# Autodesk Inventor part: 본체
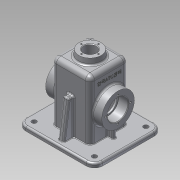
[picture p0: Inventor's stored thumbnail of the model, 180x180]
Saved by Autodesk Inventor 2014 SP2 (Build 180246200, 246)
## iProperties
Created: 2016-08
Part Number: 본체
Material: 알루미늄 6061
Document SubType Name: Modeling
Designer: 402-32
Density: 2.71 g/cm^3
Appearance: 알루미늄 - 평지
Mass: 796.088 g
Surface Area: 911.213 cm^2
Volume: 293.76 cm^3
Author: 402-32
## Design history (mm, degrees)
sketch "스케치1"
  geometry: L1 (-60, -52.5)-(60, -52.5); L2 (60, -52.5)-(60, 52.5); L3 (60, 52.5)-(-60, 52.5); L4 (-60, 52.5)-(-60, -52.5); L5 (-60, -52.5)-(60, 52.5); L6 (60, -52.5)-(-60, 52.5); 1 further point
  constraints: 12 end point, 2 midpoint, 2 parallel, 1 horizontal, 1 perpendicular
  dimensions: "d0" = 120 distance of L3.end L2.end; "d1" = 105 distance of L2.end L1.end
extrude "돌출1" new body sketch "스케치1" distance "d2" = 3; taper "d3" = 0 deg
sketch "스케치2"
  geometry: L1 (-65, -57.5)-(65, -57.5); L2 (65, -57.5)-(65, 57.5); L3 (65, 57.5)-(-65, 57.5); L4 (-65, 57.5)-(-65, -57.5); L5 (-65, -57.5)-(65, 57.5); L6 (65, -57.5)-(-65, 57.5); 1 further point
  constraints: 12 end point, 2 midpoint, 2 parallel, 1 horizontal, 1 perpendicular
  dimensions: "d4" = 130 distance of L3.end L2.end; "d5" = 115 distance of L2.end L1.end
extrude "돌출2" join sketch "스케치2" distance "d6" = 7; taper "d7" = 0 deg
sketch "스케치3"
  geometry: L1 (-32.5, -32.5)-(32.5, -32.5); L2 (32.5, -32.5)-(32.5, 32.5); L3 (32.5, 32.5)-(-32.5, 32.5); L4 (-32.5, 32.5)-(-32.5, -32.5); L5 (-32.5, -32.5)-(32.5, 32.5); L6 (32.5, -32.5)-(-32.5, 32.5); 1 further point
  constraints: 12 end point, 2 midpoint, 2 parallel, 1 horizontal, 1 perpendicular
  dimensions: "d8" = 65 distance of L3.end L2.end; "d9" = 65 distance of L2.end L1.end
extrude "돌출3" join sketch "스케치3" distance "d10" = 100; taper "d11" = 0 deg
sketch "스케치4"
  geometry: C1 r 20 at (0, 0); 1 further point
  constraints: 1 centre point, 1 coincident
  dimensions: "d12" = 40 diameter of C1
extrude "돌출4" join sketch "스케치4" distance "d13" = 10; taper "d14" = -7 deg
sketch "스케치5"
  geometry: L1 (27.5, -27.5)-(-27.5, -27.5); L2 (-27.5, -27.5)-(-27.5, 27.5); L3 (-27.5, 27.5)-(27.5, 27.5); L4 (27.5, 27.5)-(27.5, -27.5); L5 (27.5, -27.5)-(-27.5, 27.5); L6 (-27.5, -27.5)-(27.5, 27.5); 1 further point
  constraints: 12 end point, 2 midpoint, 2 parallel, 1 horizontal, 1 perpendicular
  dimensions: "d15" = 55 distance of L2.end L3.end; "d16" = 55 distance of L1.end L2.end
extrude "돌출5" cut sketch "스케치5" distance "d17" = 105; taper "d18" = 0 deg
sketch "스케치6"
  geometry: L1 (0, 65)-(0, 0) reference; L2 (-100, 0)-(-100, 65) reference; C1 r 27.5 at (-45, 32.5); 2 further points
  constraints: 1 centre point, 1 horizontal alignment, 1 midpoint
  dimensions: "d19" = 55 diameter of C1; "d20" = 45 distance from line of L1 C1.centre
extrude "돌출6" join sketch "스케치6" distance "d21" = 15; taper "d22" = 0 deg
sketch "스케치7"
  geometry: L1 (0, 65)-(0, 0) reference; L2 (0, 0)-(-100, 0) reference; L3 (0, 35.5)-(-17.664, 35.5); L4 (0, 29.5)-(-17.664, 29.5); L5 (-17.5, 32.5)-(0, 32.5); A1 r 27.5 centre (-45, 32.5) between (-17.664, 35.5) and (-17.664, 29.5) reference; 1 further point
  constraints: 6 end point, 3 point on circle, 2 parallel, 2 point on line, 1 midpoint, 1 other
  dimensions: "d23" = 6 distance between parallel lines of L3 L4
extrude "돌출7" join sketch "스케치7" distance "d24" = 10; taper "d25" = 0 deg
hole "구멍1" diameter "d28" = 21; stored, may be unused: countersink angle "d32" = 90 deg, drill point angle "d34" = 0 deg; dims "d26" = 10, "d27" = 10, "d29" = 6, "d30" = 4, "d31" = 2, "d33" = 8
hole "구멍2" diameter "d37" = 30; stored, may be unused: countersink angle "d41" = 90 deg, drill point angle "d43" = 0 deg; dims "d35" = 10, "d36" = 10, "d38" = 6, "d39" = 35, "d40" = 17, "d42" = 8
hole "구멍3" diameter "d46" = 35; stored, may be unused: countersink angle "d50" = 90 deg, drill point angle "d52" = 0 deg; dims "d44" = 10, "d45" = 10, "d47" = 6, "d48" = 35, "d49" = 17, "d51" = 17
sketch "스케치8"
  geometry: L1 (32.5, 10)-(32.5, 110) reference; L2 (57.5, 10)-(-57.5, 10) reference; L3 (32.5, 70)-(41.068, 70); L4 (41.068, 70)-(49.5, 10); L5 (57.5, 3)-(57.5, 10) reference; L6 (52.5, 0)-(-52.5, 0) reference; 1 further point
  constraints: 4 end point, 2 point on line, 1 parallel
  dimensions: "d53" = 8 distance of L2.start L4.end; "d54" = 8 deg angle of L5 L4; "d55" = 70 distance from line of L6 L3.end
extrude "돌출8" join sketch "스케치8" stored distance "d56" = 10; taper "d57" = 0 deg
sketch "스케치9"
  geometry: L1 (-10, 13.728)-(-10, 51.272) reference; A1 r 27.5 centre (55, 32.5) between (82.336, 35.5) and (82.336, 29.5) reference; 2 further points
  constraints: 1 horizontal alignment, 1 other
  dimensions: "d58" = 26 distance from line of L1 point (16, 32.5)
feature "엠보싱1" sketch "스케치9" dims "d8" = 65, "d9" = 65, "d59" = 0.5, "d60" = 0
fillet "모깎기1" dims "d61" = 9, "d62" = 14
hole "구멍4" diameter "d65" = 8; stored, may be unused: countersink angle "d69" = 90 deg, drill point angle "d71" = 0 deg; dims "d63" = 10, "d64" = 10, "d66" = 6, "d67" = 35, "d68" = 17, "d70" = 17
hole "구멍5" diameter "d74" = 8; stored, may be unused: countersink angle "d78" = 90 deg, drill point angle "d80" = 0 deg; dims "d72" = 10, "d73" = 10, "d75" = 6, "d76" = 35, "d77" = 17, "d79" = 17
hole "구멍6" diameter "d83" = 8; stored, may be unused: countersink angle "d87" = 90 deg, drill point angle "d89" = 0 deg; dims "d81" = 10, "d82" = 10, "d84" = 6, "d85" = 35, "d86" = 17, "d88" = 17
hole "구멍7" diameter "d92" = 8; stored, may be unused: countersink angle "d96" = 90 deg, drill point angle "d98" = 0 deg; dims "d90" = 10, "d91" = 10, "d93" = 6, "d94" = 35, "d95" = 17, "d97" = 17
sketch "스케치10"
  geometry: C1 r 17.5 at (0, 0) reference; 2 further points
  dimensions: "d99" = 21 distance of C1.centre point (0, 21)
hole "구멍8" sketch "스케치10" at (0, 21) diameter "d100" = 3.242; stored, may be unused: countersink angle "d104" = 90 deg, drill point angle "d106" = 118 deg; dims "d101" = 8, "d102" = 35, "d103" = 17, "d105" = 10
sketch "스케치11"
  geometry: C1 r 10.5 at (0, 0) reference; 1 further point
  dimensions: "d110" = 14.5 distance of C1.centre point (0, 14.5)
hole "구멍9" sketch "스케치11" at (0, 14.5) diameter "d111" = 2.459; stored, may be unused: countersink angle "d115" = 90 deg, drill point angle "d117" = 118 deg; dims "d112" = 7, "d113" = 35, "d114" = 17, "d116" = 9
fillet "모깎기2" dims "d121" = 3, "d122" = 8
fillet "모깎기3" dims "d123" = 3
fillet "모깎기4" dims "d124" = 3
fillet "모깎기5" dims "d125" = 3
fillet "모깎기6" dims "d126" = 1
fillet "모깎기7" dims "d127" = 0.3
chamfer "모따기1" distance "d128" = 1; stored, may be unused: second distance "d129" = 2, angle "d130" = 45 deg
node "솔리드1"
mirror "대칭1"
mirror "대칭2"
pattern_circular "원형 패턴1" dims angle "d108" = 360 deg
mirror "대칭3"
pattern_circular "원형 패턴2" dims angle "d119" = 360 deg
